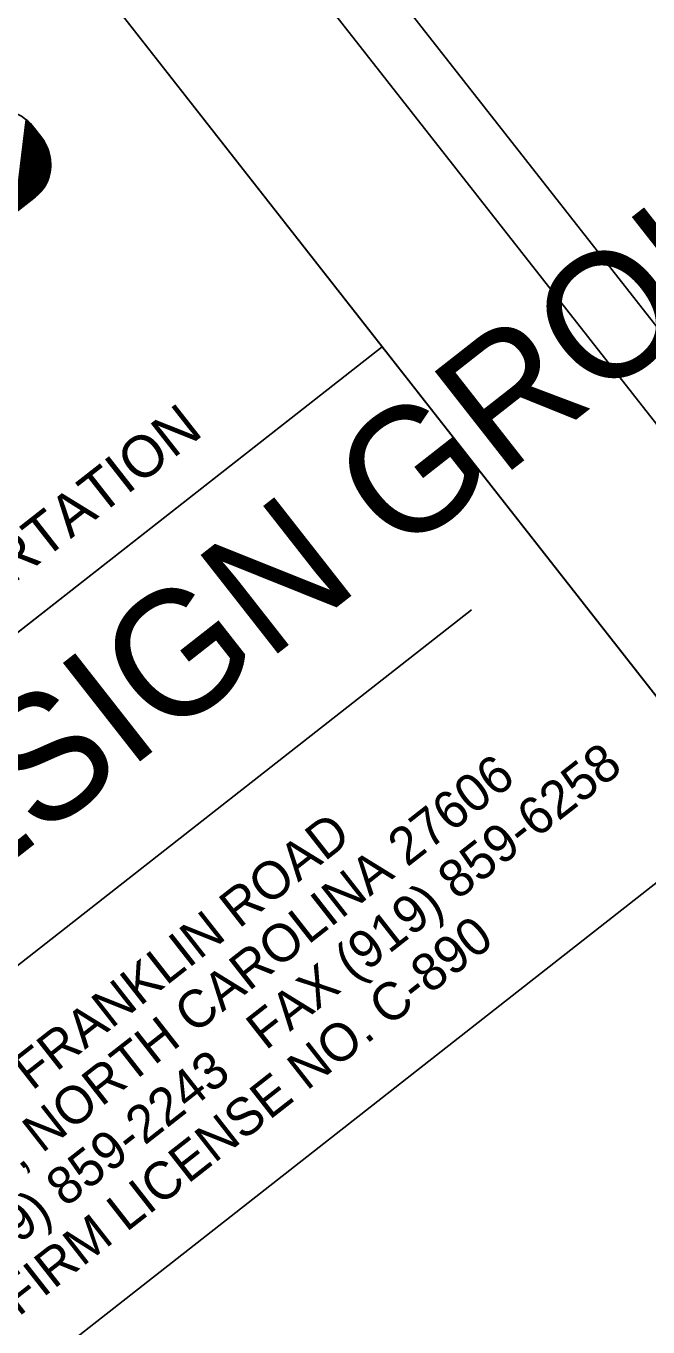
# Model space of a CAD drawing. Extents: x 2174973 to 2176977, y 76106 to 78055.
# Drawn here: x 2176411.1 to 2176457.4, y 77732.6 to 77829.5 of the extents above; entities that cross this region are included whole.
import ezdxf

# ---------------------------------------------------------------- set-up
doc = ezdxf.new("R2010")
doc.units = 0
for name, color, linetype in [('CTL Primary Horizontal CELL', 7, 'Continuous'), ('CTL Primary Horizontal Cogo Number', 7, 'Continuous'), ('Exist Other Culture Sign Cogo Point CELL', 7, 'Continuous'), ('Exist Structure Minor Storm Sewer Manhole CELL', 7, 'Continuous')]:
    doc.layers.add(name, color=color, linetype=linetype)

msp = doc.modelspace()

# ---------------------------------------------------------------- linework, layer by layer
at = {"layer": 'CTL Primary Horizontal CELL'}
msp.add_lwpolyline([(2176308.924, 77990.06), (2174997.336, 76961.974), (2175648.241, 76131.577), (2176959.829, 77159.663)], close=True, dxfattribs=at)
at = {"layer": 'CTL Primary Horizontal Cogo Number'}
msp.add_lwpolyline([(2176298.616, 78010.504), (2174973.255, 76971.623), (2175651.859, 76105.889), (2176977.22, 77144.77)], close=True, dxfattribs=at)
at = {"layer": 'Exist Other Culture Sign Cogo Point CELL'}
msp.add_line((2176391.132, 77744.405), (2176444.26, 77786.049), dxfattribs=at)
for points in [[(2176300.659, 77980.341), (2175120.112, 77054.972), (2175767.871, 76228.589), (2176948.418, 77153.958)], [(2176331.814, 77722.717), (2176437.591, 77805.63), (2176464.743, 77770.99), (2176358.966, 77688.077)]]:
    msp.add_lwpolyline(points, close=True, dxfattribs=at)
for start, end in [(38.0911, 218.0911), (218.0911, 38.0911)]:
    msp.add_arc((2176424.538, 77751.671), 0.138, start, end, dxfattribs=at)
at = {"layer": 'Exist Structure Minor Storm Sewer Manhole CELL'}
for p, q in [((2176437.591, 77805.63), (2176407.715, 77843.744)), ((2176410.246, 77815.589), (2176411.088, 77822.541)), ((2176410.257, 77815.598), (2176411.097, 77822.534)), ((2176410.268, 77815.607), (2176411.106, 77822.526)), ((2176410.279, 77815.616), (2176411.115, 77822.519)), ((2176410.29, 77815.624), (2176411.125, 77822.511)), ((2176410.301, 77815.633), (2176411.134, 77822.503)), ((2176410.312, 77815.642), (2176411.143, 77822.496)), ((2176410.324, 77815.65), (2176411.152, 77822.488)), ((2176410.335, 77815.659), (2176411.161, 77822.48)), ((2176410.346, 77815.668), (2176411.17, 77822.473)), ((2176410.357, 77815.677), (2176411.179, 77822.465)), ((2176410.368, 77815.685), (2176411.189, 77822.457)), ((2176410.379, 77815.694), (2176411.198, 77822.449)), ((2176410.39, 77815.703), (2176411.207, 77822.441)), ((2176410.401, 77815.712), (2176411.216, 77822.433)), ((2176410.413, 77815.72), (2176411.225, 77822.425)), ((2176410.424, 77815.729), (2176411.234, 77822.416)), ((2176410.435, 77815.738), (2176411.243, 77822.408)), ((2176410.446, 77815.746), (2176411.252, 77822.4)), ((2176410.457, 77815.755), (2176411.261, 77822.391)), ((2176410.468, 77815.764), (2176411.27, 77822.383)), ((2176410.479, 77815.773), (2176411.279, 77822.374)), ((2176410.49, 77815.781), (2176411.288, 77822.366)), ((2176410.502, 77815.79), (2176411.297, 77822.357)), ((2176410.513, 77815.799), (2176411.306, 77822.349)), ((2176410.524, 77815.808), (2176411.315, 77822.34)), ((2176410.535, 77815.816), (2176411.324, 77822.331)), ((2176410.546, 77815.825), (2176411.333, 77822.322)), ((2176410.557, 77815.834), (2176411.342, 77822.313)), ((2176410.568, 77815.842), (2176411.351, 77822.305)), ((2176410.58, 77815.851), (2176411.36, 77822.295)), ((2176410.591, 77815.86), (2176411.369, 77822.286)), ((2176410.602, 77815.869), (2176411.378, 77822.277)), ((2176410.613, 77815.877), (2176411.387, 77822.268)), ((2176410.624, 77815.886), (2176411.396, 77822.259)), ((2176410.635, 77815.895), (2176411.405, 77822.249)), ((2176410.646, 77815.903), (2176411.414, 77822.24)), ((2176410.657, 77815.912), (2176411.423, 77822.231)), ((2176410.669, 77815.921), (2176411.432, 77822.221)), ((2176410.68, 77815.93), (2176411.441, 77822.211)), ((2176410.691, 77815.938), (2176411.45, 77822.202)), ((2176410.702, 77815.947), (2176411.459, 77822.192)), ((2176410.713, 77815.956), (2176411.468, 77822.182)), ((2176410.724, 77815.965), (2176411.476, 77822.172)), ((2176410.735, 77815.973), (2176411.485, 77822.162)), ((2176410.746, 77815.982), (2176411.494, 77822.152)), ((2176410.758, 77815.991), (2176411.503, 77822.142)), ((2176410.769, 77815.999), (2176411.512, 77822.132)), ((2176410.78, 77816.008), (2176411.521, 77822.122)), ((2176410.791, 77816.017), (2176411.529, 77822.111)), ((2176410.802, 77816.026), (2176411.538, 77822.101)), ((2176410.813, 77816.034), (2176411.547, 77822.091)), ((2176410.824, 77816.043), (2176411.556, 77822.08)), ((2176410.836, 77816.052), (2176411.565, 77822.069)), ((2176410.847, 77816.061), (2176411.573, 77822.059)), ((2176410.858, 77816.069), (2176411.582, 77822.048)), ((2176410.869, 77816.078), (2176411.591, 77822.037)), ((2176410.88, 77816.087), (2176411.6, 77822.026)), ((2176410.891, 77816.095), (2176411.608, 77822.015)), ((2176410.902, 77816.104), (2176411.617, 77822.004)), ((2176410.913, 77816.113), (2176411.626, 77821.993)), ((2176410.925, 77816.122), (2176411.635, 77821.982)), ((2176410.936, 77816.13), (2176411.643, 77821.97)), ((2176410.947, 77816.139), (2176411.652, 77821.959)), ((2176410.958, 77816.148), (2176411.661, 77821.948)), ((2176410.969, 77816.156), (2176411.67, 77821.937)), ((2176410.98, 77816.165), (2176411.678, 77821.926)), ((2176410.991, 77816.174), (2176411.687, 77821.915)), ((2176411.002, 77816.183), (2176411.696, 77821.904)), ((2176411.014, 77816.191), (2176411.704, 77821.893)), ((2176411.025, 77816.2), (2176411.713, 77821.882)), ((2176411.036, 77816.209), (2176411.722, 77821.871)), ((2176411.047, 77816.218), (2176411.731, 77821.859)), ((2176411.058, 77816.226), (2176411.739, 77821.848)), ((2176411.069, 77816.235), (2176411.748, 77821.837)), ((2176411.08, 77816.244), (2176411.757, 77821.826)), ((2176411.092, 77816.252), (2176411.766, 77821.815)), ((2176411.103, 77816.261), (2176411.774, 77821.804)), ((2176411.114, 77816.27), (2176411.783, 77821.793)), ((2176411.125, 77816.279), (2176411.792, 77821.782)), ((2176411.136, 77816.287), (2176411.8, 77821.771)), ((2176411.147, 77816.296), (2176411.809, 77821.76)), ((2176411.158, 77816.305), (2176411.818, 77821.748)), ((2176411.169, 77816.314), (2176411.827, 77821.737)), ((2176411.181, 77816.322), (2176411.835, 77821.726)), ((2176412.181, 77821.287), (2176411.612, 77822.01)), ((2176411.192, 77816.331), (2176411.844, 77821.715)), ((2176411.203, 77816.34), (2176411.853, 77821.704)), ((2176411.214, 77816.348), (2176411.862, 77821.693)), ((2176411.225, 77816.357), (2176411.87, 77821.682)), ((2176411.236, 77816.366), (2176411.879, 77821.671)), ((2176411.247, 77816.375), (2176411.888, 77821.66)), ((2176411.258, 77816.383), (2176411.896, 77821.649)), ((2176411.27, 77816.392), (2176411.905, 77821.638)), ((2176411.281, 77816.401), (2176411.914, 77821.626)), ((2176411.292, 77816.409), (2176411.923, 77821.615)), ((2176411.303, 77816.418), (2176411.931, 77821.604)), ((2176411.314, 77816.427), (2176411.94, 77821.593)), ((2176411.325, 77816.436), (2176411.949, 77821.582)), ((2176411.336, 77816.444), (2176411.958, 77821.571)), ((2176411.348, 77816.453), (2176411.966, 77821.56)), ((2176411.359, 77816.462), (2176411.975, 77821.549)), ((2176411.37, 77816.471), (2176411.984, 77821.538)), ((2176411.381, 77816.479), (2176411.992, 77821.527)), ((2176411.392, 77816.488), (2176412.001, 77821.515)), ((2176411.403, 77816.497), (2176412.01, 77821.504)), ((2176411.414, 77816.505), (2176412.019, 77821.493)), ((2176411.425, 77816.514), (2176412.027, 77821.482)), ((2176411.437, 77816.523), (2176412.036, 77821.471)), ((2176411.448, 77816.532), (2176412.045, 77821.46)), ((2176411.459, 77816.54), (2176412.054, 77821.449)), ((2176411.47, 77816.549), (2176412.062, 77821.438)), ((2176411.481, 77816.558), (2176412.071, 77821.427)), ((2176411.492, 77816.567), (2176412.08, 77821.416)), ((2176411.503, 77816.575), (2176412.089, 77821.404)), ((2176411.514, 77816.584), (2176412.097, 77821.393)), ((2176411.526, 77816.593), (2176412.106, 77821.382)), ((2176411.537, 77816.601), (2176412.115, 77821.371)), ((2176411.548, 77816.61), (2176412.123, 77821.36)), ((2176411.559, 77816.619), (2176412.132, 77821.349)), ((2176411.57, 77816.628), (2176412.141, 77821.338)), ((2176411.581, 77816.636), (2176412.15, 77821.327)), ((2176411.592, 77816.645), (2176412.158, 77821.316)), ((2176411.604, 77816.654), (2176412.167, 77821.305)), ((2176411.615, 77816.662), (2176412.176, 77821.293)), ((2176411.626, 77816.671), (2176412.185, 77821.282)), ((2176411.637, 77816.68), (2176412.193, 77821.271)), ((2176411.648, 77816.689), (2176412.202, 77821.26)), ((2176411.659, 77816.697), (2176412.211, 77821.249)), ((2176411.67, 77816.706), (2176412.219, 77821.237)), ((2176411.681, 77816.715), (2176412.228, 77821.226)), ((2176411.693, 77816.724), (2176412.237, 77821.214)), ((2176411.704, 77816.732), (2176412.245, 77821.202)), ((2176411.715, 77816.741), (2176412.254, 77821.19)), ((2176411.726, 77816.75), (2176412.263, 77821.179)), ((2176411.737, 77816.758), (2176412.271, 77821.167)), ((2176411.748, 77816.767), (2176412.28, 77821.155)), ((2176411.759, 77816.776), (2176412.288, 77821.142)), ((2176411.77, 77816.785), (2176412.297, 77821.13)), ((2176411.782, 77816.793), (2176412.306, 77821.118)), ((2176411.793, 77816.802), (2176412.314, 77821.105)), ((2176411.804, 77816.811), (2176412.323, 77821.093)), ((2176411.815, 77816.82), (2176412.331, 77821.08)), ((2176411.826, 77816.829), (2176412.34, 77821.067)), ((2176411.837, 77816.838), (2176412.348, 77821.055)), ((2176411.849, 77816.847), (2176412.357, 77821.042)), ((2176411.86, 77816.856), (2176412.365, 77821.029)), ((2176411.871, 77816.866), (2176412.374, 77821.015)), ((2176411.882, 77816.875), (2176412.382, 77821.002)), ((2176411.893, 77816.885), (2176412.391, 77820.989)), ((2176411.905, 77816.895), (2176412.399, 77820.975)), ((2176411.916, 77816.904), (2176412.408, 77820.962)), ((2176411.927, 77816.914), (2176412.416, 77820.948)), ((2176411.939, 77816.924), (2176412.424, 77820.934)), ((2176411.95, 77816.935), (2176412.433, 77820.92)), ((2176411.961, 77816.945), (2176412.441, 77820.906)), ((2176411.972, 77816.955), (2176412.449, 77820.892)), ((2176411.984, 77816.966), (2176412.458, 77820.878)), ((2176411.995, 77816.977), (2176412.466, 77820.863)), ((2176412.007, 77816.988), (2176412.474, 77820.848)), ((2176412.018, 77816.999), (2176412.483, 77820.834)), ((2176412.029, 77817.01), (2176412.491, 77820.819)), ((2176412.041, 77817.021), (2176412.499, 77820.804)), ((2176412.052, 77817.032), (2176412.507, 77820.789)), ((2176412.064, 77817.044), (2176412.516, 77820.773)), ((2176412.075, 77817.056), (2176412.524, 77820.758)), ((2176412.087, 77817.067), (2176412.532, 77820.742)), ((2176412.098, 77817.079), (2176412.54, 77820.727)), ((2176412.11, 77817.092), (2176412.548, 77820.711)), ((2176412.121, 77817.104), (2176412.557, 77820.695)), ((2176412.133, 77817.116), (2176412.565, 77820.678)), ((2176412.145, 77817.129), (2176412.573, 77820.662)), ((2176412.156, 77817.142), (2176412.581, 77820.645)), ((2176412.168, 77817.155), (2176412.589, 77820.628)), ((2176412.18, 77817.168), (2176412.597, 77820.611)), ((2176412.191, 77817.182), (2176412.605, 77820.594)), ((2176412.203, 77817.195), (2176412.613, 77820.577)), ((2176412.215, 77817.209), (2176412.621, 77820.559)), ((2176412.227, 77817.223), (2176412.629, 77820.542)), ((2176412.238, 77817.237), (2176412.637, 77820.524)), ((2176412.25, 77817.252), (2176412.644, 77820.505)), ((2176412.262, 77817.266), (2176412.652, 77820.487)), ((2176412.274, 77817.281), (2176412.66, 77820.468)), ((2176412.286, 77817.296), (2176412.668, 77820.449)), ((2176412.298, 77817.312), (2176412.676, 77820.43)), ((2176412.31, 77817.328), (2176412.683, 77820.411)), ((2176412.322, 77817.343), (2176412.691, 77820.391)), ((2176412.334, 77817.36), (2176412.699, 77820.371)), ((2176412.346, 77817.376), (2176412.706, 77820.351)), ((2176412.358, 77817.393), (2176412.714, 77820.33)), ((2176412.37, 77817.41), (2176412.721, 77820.31)), ((2176412.382, 77817.427), (2176412.729, 77820.288)), ((2176412.394, 77817.445), (2176412.736, 77820.267)), ((2176412.407, 77817.463), (2176412.744, 77820.245)), ((2176412.419, 77817.482), (2176412.751, 77820.223)), ((2176412.431, 77817.501), (2176412.759, 77820.2)), ((2176412.444, 77817.52), (2176412.766, 77820.177)), ((2176412.456, 77817.539), (2176412.773, 77820.154)), ((2176412.469, 77817.559), (2176412.78, 77820.13)), ((2176412.481, 77817.58), (2176412.787, 77820.106)), ((2176412.494, 77817.601), (2176412.794, 77820.081)), ((2176412.507, 77817.623), (2176412.801, 77820.056)), ((2176412.519, 77817.645), (2176412.808, 77820.03)), ((2176412.532, 77817.667), (2176412.815, 77820.003)), ((2176412.545, 77817.691), (2176412.822, 77819.976)), ((2176412.558, 77817.715), (2176412.829, 77819.949)), ((2176412.571, 77817.739), (2176412.835, 77819.92)), ((2176412.584, 77817.765), (2176412.842, 77819.891)), ((2176412.598, 77817.791), (2176412.848, 77819.861)), ((2176412.611, 77817.818), (2176412.855, 77819.83)), ((2176412.624, 77817.846), (2176412.861, 77819.799)), ((2176412.638, 77817.875), (2176412.867, 77819.766)), ((2176412.652, 77817.905), (2176412.873, 77819.732)), ((2176412.666, 77817.937), (2176412.879, 77819.697)), ((2176412.68, 77817.97), (2176412.884, 77819.66)), ((2176412.694, 77818.004), (2176412.89, 77819.622)), ((2176412.708, 77818.04), (2176412.895, 77819.581)), ((2176412.723, 77818.079), (2176412.9, 77819.539)), ((2176412.738, 77818.12), (2176412.905, 77819.494)), ((2176412.754, 77818.164), (2176412.909, 77819.446)), ((2176412.769, 77818.212), (2176412.913, 77819.395)), ((2176412.786, 77818.265), (2176412.916, 77819.338)), ((2176412.803, 77818.324), (2176412.918, 77819.276)), ((2176412.821, 77818.392), (2176412.92, 77819.204)), ((2176412.842, 77818.475), (2176412.919, 77819.117)), ((2176412.866, 77818.593), (2176412.915, 77818.995)), ((2176406.39, 77812.567), (2176411.792, 77816.802)), ((2176437.591, 77805.63), (2176331.814, 77722.717))]:
    msp.add_line(p, q, dxfattribs=at)
for centre, major_axis, start_param, end_param in [((2176409.362, 77820.247), (-1.888, 2.409), 4.712389, 6.225205), ((2176409.763, 77819.391), (-2.03, 2.589), 3.141593, 4.712389)]:
    msp.add_ellipse(centre, major_axis=major_axis, ratio=0.934072, start_param=start_param, end_param=end_param, dxfattribs=at)

# ---------------------------------------------------------------- texts
at = {"layer": 'Exist Other Culture Sign Cogo Point CELL'}
for s, height, p in [('SUNGATE DESIGN GROUP, P.A.', 9.31938, (2176348.366, 77718.933)), ('RALEIGH, NORTH CAROLINA 27606', 2.80071, (2176397.688, 77734.1)), ('TEL (919) 859-2243   FAX (919) 859-6258', 2.80071, (2176400.084, 77730.583)), ('905 JONES FRANKLIN ROAD', 2.80071, (2176395.145, 77737.344)), ('ENG FIRM LICENSE NO. C-890', 2.80071, (2176403.317, 77727.721))]:
    msp.add_text(s, height=height, rotation=38.0911, dxfattribs=at).set_placement(p)
at = {"layer": 'Exist Structure Minor Storm Sewer Manhole CELL'}
msp.add_text('FOR NORTH CAROLINA DEPT. OF TRANSPORTATION', height=3.10128, rotation=38.09105, dxfattribs=at).set_placement((2176340.411, 77733.297))

doc.saveas('drawing.dxf')
